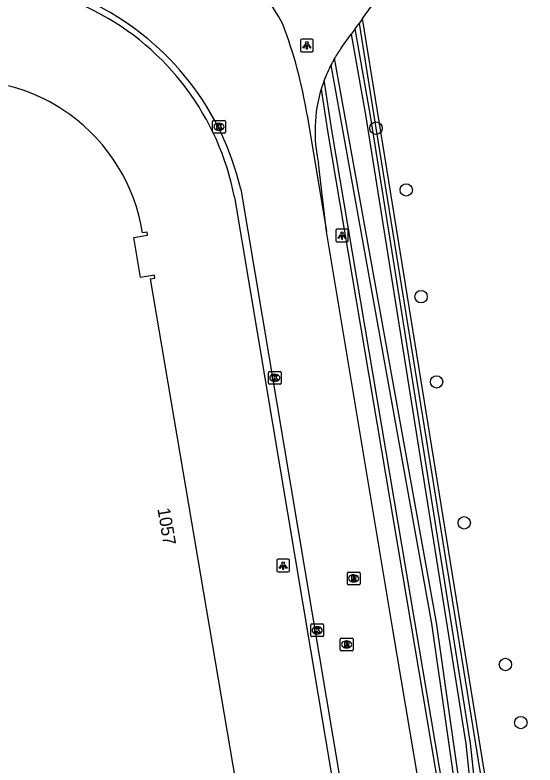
# Model space of a CAD drawing. Extents: x 154324 to 155743, y 382939 to 384183.
# Drawn here: x 154972.4 to 155013.4, y 383820.7 to 383879.9 of the extents above; entities that cross this region are included whole.
import ezdxf

# ---------------------------------------------------------------- set-up
doc = ezdxf.new("R2010")
doc.units = 0
for name, color, linetype in [('IMGEO_Boom', 7, 'Continuous'), ('IMGEO_Gemengd_bos', 7, 'Continuous'), ('IMGEO_Groenvoorziening', 7, 'Continuous'), ('IMGEO_Kolk', 7, 'Continuous'), ('IMGEO_Lichtpunt', 7, 'Continuous'), ('IMGEO_Pand', 7, 'Continuous'), ('IMGEO_Pand_nummerreeks', 7, 'Continuous'), ('IMGEO_Rijbaan_lokaal_gesloten', 7, 'Continuous'), ('IMGEO_Rijbaan_lokaal_open', 7, 'Continuous'), ('IMGEO_Rioolput', 7, 'Continuous'), ('IMGEO_Waterloop', 7, 'Continuous')]:
    doc.layers.add(name, color=color, linetype=linetype)

msp = doc.modelspace()

# ---------------------------------------------------------------- linework, layer by layer
at = {"layer": 'IMGEO_Boom'}
for centre in [(155000.837, 383870.939), (155003.225, 383866.07), (155004.392, 383857.656), (155005.618, 383850.94), (155007.794, 383839.829), (155011.045, 383828.66), (155012.255, 383824.082)]:
    msp.add_circle(centre, 0.489, dxfattribs=at)
at = {"layer": 'IMGEO_Gemengd_bos'}
msp.add_lwpolyline([(154998.88, 383878.344), (155000.011, 383871.994), (155007.915, 383822.409), (155008.825, 383813.835), (155008.833, 383813.728), (155009.111, 383807.437), (155005.612, 383831.964), (154997.582, 383876.452)], dxfattribs=at)
at = {"layer": 'IMGEO_Groenvoorziening'}
for points in [[(155010.749, 383800.586), (155010.405, 383813.833), (154999.781, 383879.589)], [(154996.525, 383874.017), (154997.022, 383870.738), (155006.822, 383812.702), (155008.779, 383799.869)]]:
    msp.add_lwpolyline(points, dxfattribs=at)
at = {"layer": 'IMGEO_Kolk'}
for p, q in [((154987.965, 383870.621), (154987.965, 383871.473)), ((154988.04, 383871.547), (154988.892, 383871.547)), ((154988.453, 383871.327), (154988.478, 383871.327)), ((154988.966, 383871.473), (154988.966, 383870.621)), ((154988.892, 383870.547), (154988.04, 383870.547)), ((154988.476, 383870.767), (154988.451, 383870.767)), ((154992.361, 383850.831), (154992.361, 383851.683)), ((154992.436, 383851.757), (154993.288, 383851.757)), ((154992.849, 383851.537), (154992.874, 383851.537)), ((154993.362, 383851.683), (154993.362, 383850.831)), ((154992.872, 383850.977), (154992.847, 383850.977)), ((154993.288, 383850.757), (154992.436, 383850.757)), ((154995.701, 383830.932), (154995.701, 383831.784)), ((154995.776, 383831.858), (154996.628, 383831.858)), ((154996.189, 383831.638), (154996.214, 383831.638)), ((154996.702, 383831.784), (154996.702, 383830.932)), ((154996.628, 383830.858), (154995.776, 383830.858)), ((154996.212, 383831.078), (154996.187, 383831.078))]:
    msp.add_line(p, q, dxfattribs=at)
for points in [[(154987.965, 383870.621), (154987.965, 383871.473)], [(154988.04, 383871.547), (154988.892, 383871.547)], [(154988.286, 383871.247), (154988.409, 383871.247), (154988.409, 383871.096), (154988.539, 383871.247), (154988.703, 383871.247), (154988.557, 383871.096), (154988.71, 383870.847), (154988.558, 383870.847), (154988.473, 383871.011), (154988.409, 383870.944), (154988.409, 383870.847), (154988.286, 383870.847), (154988.286, 383871.247)], [(154988.966, 383871.473), (154988.966, 383870.621)], [(154988.892, 383870.547), (154988.04, 383870.547)], [(154992.361, 383850.831), (154992.361, 383851.683)], [(154992.436, 383851.757), (154993.288, 383851.757)], [(154993.362, 383851.683), (154993.362, 383850.831)], [(154992.682, 383851.457), (154992.805, 383851.457), (154992.805, 383851.306), (154992.935, 383851.457), (154993.099, 383851.457), (154992.953, 383851.306), (154993.106, 383851.057), (154992.954, 383851.057), (154992.869, 383851.221), (154992.805, 383851.154), (154992.805, 383851.057), (154992.682, 383851.057), (154992.682, 383851.457)], [(154993.288, 383850.757), (154992.436, 383850.757)], [(154995.701, 383830.932), (154995.701, 383831.784)], [(154995.776, 383831.858), (154996.628, 383831.858)], [(154996.022, 383831.558), (154996.145, 383831.558), (154996.145, 383831.407), (154996.275, 383831.558), (154996.439, 383831.558), (154996.293, 383831.407), (154996.446, 383831.158), (154996.294, 383831.158), (154996.209, 383831.322), (154996.145, 383831.255), (154996.145, 383831.158), (154996.022, 383831.158), (154996.022, 383831.558)], [(154996.702, 383831.784), (154996.702, 383830.932)], [(154996.628, 383830.858), (154995.776, 383830.858)]]:
    msp.add_lwpolyline(points, dxfattribs=at)
for centre, start, end in [((154988.042, 383871.471), 91.55205, 178.44795), ((154988.042, 383871.471), 91.55205, 178.44795), ((154988.89, 383871.471), 1.55205, 88.44795), ((154988.89, 383871.471), 1.55205, 88.44795), ((154988.042, 383870.623), 181.55205, 268.44795), ((154988.042, 383870.623), 181.55205, 268.44795), ((154988.89, 383870.623), 271.55205, 358.44795), ((154988.89, 383870.623), 271.55205, 358.44795), ((154992.438, 383851.681), 91.55205, 178.44795), ((154992.438, 383851.681), 91.55205, 178.44795), ((154993.286, 383851.681), 1.55205, 88.44795), ((154993.286, 383851.681), 1.55205, 88.44795), ((154992.438, 383850.833), 181.55205, 268.44795), ((154992.438, 383850.833), 181.55205, 268.44795), ((154993.286, 383850.833), 271.55205, 358.44795), ((154993.286, 383850.833), 271.55205, 358.44795), ((154995.778, 383831.782), 91.55205, 178.44795), ((154995.778, 383831.782), 91.55205, 178.44795), ((154996.626, 383831.782), 1.55205, 88.44795), ((154996.626, 383831.782), 1.55205, 88.44795), ((154995.778, 383830.934), 181.55205, 268.44795), ((154995.778, 383830.934), 181.55205, 268.44795), ((154996.626, 383830.934), 271.55205, 358.44795), ((154996.626, 383830.934), 271.55205, 358.44795)]:
    msp.add_arc(centre, 0.0765, start, end, dxfattribs=at)
for centre, major_axis, ratio, start_param, end_param in [((154988.452, 383871.047), (-0.387, 0.002), 0.722429, 4.712389, 7.853982), ((154988.477, 383871.047), (-0.39, 0.002), 0.717154, 1.570796, 4.712389), ((154992.848, 383851.257), (-0.387, 0.002), 0.722429, 4.712389, 7.853982), ((154992.873, 383851.257), (-0.39, 0.002), 0.717154, 1.570796, 4.712389), ((154996.188, 383831.358), (-0.387, 0.002), 0.722429, 4.712389, 7.853982), ((154996.213, 383831.358), (-0.39, 0.002), 0.717154, 1.570796, 4.712389)]:
    msp.add_ellipse(centre, major_axis=major_axis, ratio=ratio, start_param=start_param, end_param=end_param, dxfattribs=at)
at = {"layer": 'IMGEO_Lichtpunt'}
for p, q in [((154994.897, 383877.863), (154994.897, 383877.056)), ((154994.897, 383877.863), (154994.897, 383877.056)), ((154995.799, 383877.958), (154994.991, 383877.958)), ((154995.799, 383877.958), (154994.991, 383877.958)), ((154995.893, 383877.056), (154995.893, 383877.863)), ((154995.893, 383877.056), (154995.893, 383877.863)), ((154994.991, 383876.962), (154995.799, 383876.962)), ((154994.991, 383876.962), (154995.799, 383876.962)), ((154997.663, 383862.879), (154997.663, 383862.072)), ((154997.663, 383862.879), (154997.663, 383862.072)), ((154998.565, 383862.974), (154997.757, 383862.974)), ((154998.565, 383862.974), (154997.757, 383862.974)), ((154998.659, 383862.072), (154998.659, 383862.879)), ((154998.659, 383862.072), (154998.659, 383862.879)), ((154997.757, 383861.978), (154998.565, 383861.978)), ((154997.757, 383861.978), (154998.565, 383861.978)), ((154993.024, 383836.86), (154993.024, 383836.053)), ((154993.024, 383836.86), (154993.024, 383836.053)), ((154993.926, 383836.955), (154993.118, 383836.955)), ((154993.926, 383836.955), (154993.118, 383836.955)), ((154994.02, 383836.053), (154994.02, 383836.86)), ((154994.02, 383836.053), (154994.02, 383836.86)), ((154993.118, 383835.959), (154993.926, 383835.959)), ((154993.118, 383835.959), (154993.926, 383835.959))]:
    msp.add_line(p, q, dxfattribs=at)
for points in [[(154995.271, 383877.527), (154995.31, 383877.499), (154995.122, 383877.237), (154995.084, 383877.264), (154995.271, 383877.527)], [(154995.373, 383877.479), (154995.42, 383877.479), (154995.42, 383877.157), (154995.373, 383877.157), (154995.373, 383877.479)], [(154995.483, 383877.499), (154995.521, 383877.526), (154995.708, 383877.264), (154995.669, 383877.236), (154995.483, 383877.499)], [(154998.037, 383862.543), (154998.076, 383862.515), (154997.888, 383862.253), (154997.85, 383862.28), (154998.037, 383862.543)], [(154998.139, 383862.495), (154998.186, 383862.495), (154998.186, 383862.173), (154998.139, 383862.173), (154998.139, 383862.495)], [(154998.249, 383862.515), (154998.287, 383862.542), (154998.474, 383862.28), (154998.435, 383862.252), (154998.249, 383862.515)], [(154993.398, 383836.524), (154993.437, 383836.496), (154993.249, 383836.234), (154993.211, 383836.261), (154993.398, 383836.524)], [(154993.5, 383836.476), (154993.547, 383836.476), (154993.547, 383836.154), (154993.5, 383836.154), (154993.5, 383836.476)], [(154993.61, 383836.496), (154993.648, 383836.523), (154993.835, 383836.261), (154993.796, 383836.233), (154993.61, 383836.496)]]:
    msp.add_lwpolyline(points, dxfattribs=at)
for centre in [(154995.396, 383877.661), (154998.162, 383862.677), (154993.523, 383836.658)]:
    msp.add_circle(centre, 0.0994, dxfattribs=at)
for centre, start, end in [((154994.991, 383877.863), 90, 180), ((154994.991, 383877.863), 90, 180), ((154995.799, 383877.863), 0, 90), ((154995.799, 383877.863), 0, 90), ((154994.991, 383877.056), 180, 270), ((154994.991, 383877.056), 180, 270), ((154995.799, 383877.056), 270, 0), ((154995.799, 383877.056), 270, 360), ((154997.757, 383862.879), 90, 180), ((154997.757, 383862.879), 90, 180), ((154998.565, 383862.879), 0, 90), ((154998.565, 383862.879), 0, 90), ((154997.757, 383862.072), 180, 270), ((154997.757, 383862.072), 180, 270), ((154998.565, 383862.072), 270, 0), ((154998.565, 383862.072), 270, 360), ((154993.118, 383836.86), 90, 180), ((154993.118, 383836.86), 90, 180), ((154993.926, 383836.86), 0, 90), ((154993.926, 383836.86), 0, 90), ((154993.118, 383836.053), 180, 270), ((154993.118, 383836.053), 180, 270), ((154993.926, 383836.053), 270, 0), ((154993.926, 383836.053), 270, 360)]:
    msp.add_arc(centre, 0.0946, start, end, dxfattribs=at)
at = {"layer": 'IMGEO_Pand'}
msp.add_lwpolyline([(154990.053, 383817.92), (154983.065, 383859.056), (154983.42, 383859.114), (154983.382, 383859.351), (154982.276, 383859.173), (154981.758, 383862.33), (154982.843, 383862.511), (154982.803, 383862.747), (154982.447, 383862.688)], dxfattribs=at)
for centre, radius, start, end in [((154968.564, 383860.875), 13.795, 53.84566, 114.75354), ((154968.262, 383860.383), 14.371, 9.2287, 54.03016)]:
    msp.add_arc(centre, radius, start, end, dxfattribs=at)
at = {"layer": 'IMGEO_Rijbaan_lokaal_gesloten'}
for points in [[(154999.781, 383879.589), (155001.914, 383882.537), (155002.919, 383883.925), (155004.825, 383886.546)], [(154999.781, 383879.589), (154999.501, 383879.202)], [(154999.197, 383878.781), (154998.88, 383878.344)], [(154999.197, 383878.781), (154999.501, 383879.202)], [(154998.126, 383877.302), (154998.88, 383878.344)], [(154995.411, 383871.976), (154996.943, 383862.793)], [(154996.943, 383862.793), (154996.312, 383868.192)], [(154990.18, 383866.132), (155008.692, 383756.004)], [(155013.373, 383763.974), (155010.136, 383783.072), (155010.285, 383783.102), (155007.976, 383797.016), (155002.174, 383831.432), (154996.943, 383862.793)]]:
    msp.add_lwpolyline(points, dxfattribs=at)
for centre, radius, start, end in [((154968.895, 383861.158), 21.858, 13.15331, 112.43509), ((154973.044, 383868.176), 23.201, 28.19104, 41.12856), ((154959.519, 383866.198), 36.354, 9.14486, 20.84743), ((155007.047, 383870.993), 10.927, 144.73392, 150.02759), ((155008.585, 383870.102), 12.704, 150.01187, 152.81142), ((155007.312, 383870.781), 11.261, 152.92472, 159.54403), ((155006.86, 383870.922), 10.788, 159.40686, 163.3308), ((155007.497, 383870.699), 11.462, 163.17576, 192.63589)]:
    msp.add_arc(centre, radius, start, end, dxfattribs=at)
at = {"layer": 'IMGEO_Rijbaan_lokaal_open'}
msp.add_lwpolyline([(154989.689, 383865.488), (154997.464, 383819.179)], dxfattribs=at)
msp.add_arc((154969.058, 383861.488), 21.015, 10.97244, 114.49876, dxfattribs=at)
at = {"layer": 'IMGEO_Rioolput'}
for p, q in [((154998.583, 383835.02), (154998.583, 383835.872)), ((154998.658, 383835.946), (154999.51, 383835.946)), ((154999.071, 383835.726), (154999.096, 383835.726)), ((154999.584, 383835.872), (154999.584, 383835.02)), ((154999.094, 383835.166), (154999.069, 383835.166)), ((154999.51, 383834.946), (154998.658, 383834.946)), ((154998.029, 383829.816), (154998.029, 383830.668)), ((154998.104, 383830.742), (154998.956, 383830.742)), ((154998.517, 383830.522), (154998.542, 383830.522)), ((154999.03, 383830.668), (154999.03, 383829.816)), ((154998.956, 383829.742), (154998.104, 383829.742)), ((154998.54, 383829.962), (154998.515, 383829.962))]:
    msp.add_line(p, q, dxfattribs=at)
for points in [[(154998.583, 383835.02), (154998.583, 383835.872)], [(154998.658, 383835.946), (154999.51, 383835.946)], [(154999.172, 383835.644), (154998.92, 383835.646), (154998.92, 383835.246)], [(154999.098, 383835.565), (154999.044, 383835.565), (154999.044, 383835.484)], [(154999.584, 383835.872), (154999.584, 383835.02)], [(154998.92, 383835.246), (154999.044, 383835.246), (154999.044, 383835.408), (154999.055, 383835.408)], [(154999.044, 383835.484), (154999.096, 383835.484)], [(154999.102, 383835.379), (154999.173, 383835.246), (154999.313, 383835.246), (154999.248, 383835.372)], [(154999.51, 383834.946), (154998.658, 383834.946)], [(154998.029, 383829.816), (154998.029, 383830.668)], [(154998.104, 383830.742), (154998.956, 383830.742)], [(154998.618, 383830.44), (154998.366, 383830.442), (154998.366, 383830.042)], [(154998.544, 383830.361), (154998.49, 383830.361), (154998.49, 383830.28)], [(154998.49, 383830.28), (154998.542, 383830.28)], [(154999.03, 383830.668), (154999.03, 383829.816)], [(154998.956, 383829.742), (154998.104, 383829.742)], [(154998.366, 383830.042), (154998.49, 383830.042), (154998.49, 383830.204), (154998.501, 383830.204)], [(154998.548, 383830.175), (154998.619, 383830.042), (154998.759, 383830.042), (154998.694, 383830.168)]]:
    msp.add_lwpolyline(points, dxfattribs=at)
for centre, radius, start, end in [((154998.66, 383835.87), 0.0765, 91.55205, 178.44795), ((154998.66, 383835.87), 0.0765, 91.55205, 178.44795), ((154999.104, 383835.469), 0.0964, 77.00612, 93.18647), ((154999.118, 383835.526), 0.0378, 276.66336, 79.67722), ((154999.171, 383835.534), 0.109, 350.36119, 89.41601), ((154999.508, 383835.87), 0.0765, 1.55205, 88.44795), ((154999.508, 383835.87), 0.0765, 1.55205, 88.44795), ((154998.66, 383835.022), 0.0765, 181.55205, 268.44795), ((154998.66, 383835.022), 0.0765, 181.55205, 268.44795), ((154999.054, 383835.355), 0.0533, 26.02933, 88.69889), ((154999.08, 383835.673), 0.19, 274.7715, 282.96867), ((154999.169, 383835.534), 0.112, 277.58423, 350.98172), ((154999.153, 383835.319), 0.108, 29.51342, 73.79051), ((154999.508, 383835.022), 0.0765, 271.55205, 358.44795), ((154999.508, 383835.022), 0.0765, 271.55205, 358.44795), ((154998.106, 383830.666), 0.0765, 91.55205, 178.44795), ((154998.106, 383830.666), 0.0765, 91.55205, 178.44795), ((154998.526, 383830.469), 0.19, 274.7715, 282.96867), ((154998.55, 383830.265), 0.0964, 77.00612, 93.18647), ((154998.564, 383830.322), 0.0378, 276.66336, 79.67722), ((154998.617, 383830.33), 0.109, 350.36119, 89.41601), ((154998.615, 383830.33), 0.112, 277.58423, 350.98172), ((154998.954, 383830.666), 0.0765, 1.55205, 88.44795), ((154998.954, 383830.666), 0.0765, 1.55205, 88.44795), ((154998.106, 383829.818), 0.0765, 181.55205, 268.44795), ((154998.106, 383829.818), 0.0765, 181.55205, 268.44795), ((154998.5, 383830.151), 0.0533, 26.02933, 88.69889), ((154998.599, 383830.115), 0.108, 29.51342, 73.79051), ((154998.954, 383829.818), 0.0765, 271.55205, 358.44795), ((154998.954, 383829.818), 0.0765, 271.55205, 358.44795)]:
    msp.add_arc(centre, radius, start, end, dxfattribs=at)
for centre, major_axis, ratio, start_param, end_param in [((154999.07, 383835.446), (-0.387, 0.002), 0.722429, 4.712389, 7.853982), ((154999.095, 383835.446), (-0.39, 0.002), 0.717154, 1.570796, 4.712389), ((154998.516, 383830.242), (-0.387, 0.002), 0.722429, 4.712389, 7.853982), ((154998.541, 383830.242), (-0.39, 0.002), 0.717154, 1.570796, 4.712389)]:
    msp.add_ellipse(centre, major_axis=major_axis, ratio=ratio, start_param=start_param, end_param=end_param, dxfattribs=at)
at = {"layer": 'IMGEO_Waterloop'}
for points in [[(154997.285, 383875.907), (155005.228, 383831.902), (155008.867, 383806.395), (155009.545, 383806.425), (155009.221, 383813.751), (155009.212, 383813.87), (155008.3, 383822.46), (155000.394, 383872.059), (154999.197, 383878.781)], [(154999.501, 383879.202), (155000.837, 383870.939), (155010.067, 383813.801), (155010.409, 383800.612)], [(155009.11, 383799.946), (155007.157, 383812.756), (154997.357, 383870.792), (154996.761, 383874.717)]]:
    msp.add_lwpolyline(points, dxfattribs=at)

# ---------------------------------------------------------------- texts
at = {"layer": 'IMGEO_Pand_nummerreeks'}
msp.add_text('1057', height=1, rotation=279.64267, dxfattribs=at).set_placement((154983.608, 383840.93))

doc.saveas('drawing.dxf')
